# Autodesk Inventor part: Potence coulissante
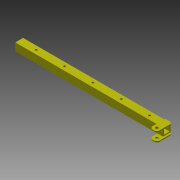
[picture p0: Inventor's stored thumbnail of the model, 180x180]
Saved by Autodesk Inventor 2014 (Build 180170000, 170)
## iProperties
Created: 2015-06
Part Number: Potence coulissante
Material: Générique
Document SubType Name: Modeling
Designer: OL
Density: 1 g/cm^3
Appearance: Par défaut
Author: OL
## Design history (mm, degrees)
sketch "Esquisse1"
  geometry: L1 (-27.5, 27.5)-(27.5, 27.5); L2 (27.5, 27.5)-(27.5, -27.5); L3 (27.5, -27.5)-(-27.5, -27.5); L4 (-27.5, -27.5)-(-27.5, 27.5); L5 (20, -20)-(-20, -20); L6 (-20, -20)-(-20, 20); L7 (-20, 20)-(20, 20); L8 (20, 20)-(20, -20); 1 further point
  constraints: 16 end point, 4 parallel, 2 horizontal, 2 perpendicular
  dimensions: "d0" = 7.5 distance between parallel lines of L1 L7; "d2" = 55 distance of L1.end L2.end; "d3" = 27.5 distance from line of L3 point (0, 0) (= 0.5 x d2); "d4" = 55 distance of L1.start L1.end (= d2); "d5" = 27.5 distance from line of L2 point (0, 0) (= d3); "d6" = 7.5 distance between parallel lines of L2 L8 (= d0); "d7" = 7.5 distance between parallel lines of L4 L6 (= d0); "d8" = 7.5 distance between parallel lines of L3 L5 (= d0)
extrude "Extrusion1" new body sketch "Esquisse1" distance "d9" = 1042; taper "d10" = 0 deg
sketch "Esquisse2"
  geometry: L1 (1042, 55)-(1042, 0) reference; L2 (0, 55)-(1042, 55) reference; L3 (1004, 55)-(1042, 55); L4 (1054, 43)-(1054, -43); L5 (1042, -55)-(1016, -55); L6 (1004, -43)-(1004, 55); L7 (1042, 55)-(1054, 43); L8 (1016, -55)-(1004, -43); L9 (1054, -43)-(1042, -55); C1 r 10 at (1029, -30); 3 further points; 1 other entity
  constraints: 14 end point, 3 parallel, 1 centre point, 1 coincident, 1 horizontal, 1 perpendicular, 1 point on line, 2 other
  dimensions: "d11" = 110 distance between parallel lines of L5 L3; "d13" = 12 horizontal distance of L3.end L4.start; "d14" = 12 horizontal distance of L3.end L4.start; "d15" = 12 horizontal distance of L5.end L6.start; "d16" = 0.21346 dimension on L6; "d17" = 50 distance between parallel lines of L4 L6; "d18" = 12 horizontal distance of L4.end L5.start; "d19" = 12 horizontal distance of L4.end L5.start; "d20" = 12 distance between parallel lines of L4 L1; "d21" = 20 diameter of C1; "d22" = 25 distance from line of L5 C1.centre; "d23" = 25 distance from line of L4 C1.centre
extrude "Extrusion2" join sketch "Esquisse2" distance "d24" = 7.5; taper "d25" = 0 deg
mirror "Symétrie1"
sketch "Esquisse3"
  geometry: L1 (0, 0)-(1004, 0) reference; L2 (1054, -43)-(1054, 43) reference; C1 r 8 at (920, 27.5); C2 r 8 at (720, 27.5); C3 r 8 at (520, 27.5); C4 r 8 at (120, 27.5); C5 r 8 at (320, 27.5); 1 further point
  constraints: 5 centre point
  dimensions: "d26" = 16 diameter of C1; "d28" = 134 distance from line of L2 C1.centre; "d29" = 27.5 distance from line of L1 C1.centre; "d30" = 200 distance of C1.centre C2.centre; "d31" = 200 distance of C2.centre C3.centre; "d32" = 200 distance of C3.centre C5.centre; "d33" = 16 diameter of C2; "d34" = 16 diameter of C3; "d35" = 16 diameter of C5; "d36" = 200 distance of C4.centre C5.centre; "d37" = 16 diameter of C4; "d38" = 27.5 distance from line of L1 C4.centre; "d39" = 27.5 distance from line of L1 C5.centre; "d40" = 27.5 distance from line of L1 C3.centre; "d41" = 27.5 distance from line of L1 C2.centre
extrude "Extrusion3" cut sketch "Esquisse3" stored distance "d42" = 0; taper "d43" = 0 deg
node "Solide1"
